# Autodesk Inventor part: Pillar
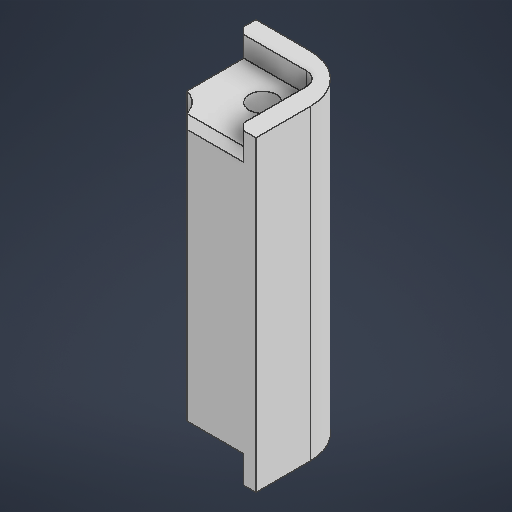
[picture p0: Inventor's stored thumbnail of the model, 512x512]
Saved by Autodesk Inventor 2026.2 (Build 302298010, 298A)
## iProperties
Created: 2026-04
Part Number: Pillar
Material: 일반
Document SubType Name: Modeling
Designer: work
Density: 1 g/cm^3
Appearance: 기본값
Author: work
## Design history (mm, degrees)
sketch "스케치1"
  geometry: L1 (0, 0)-(8, 0); L2 (0, 0)-(0, 8); L3 (8, 4)-(8, -7); L4 (8, -7)-(0, -7); L5 (8, 4)-(4, 4); L6 (4, 4)-(4, 8); L7 (4, 8)-(-7, 8); L8 (-7, 8)-(-7, 0); L9 (0, 0)-(-7, 0); L10 (0, 0)-(0, -7); C1 r 2 at (0, 0); A1 r 7 centre (0, 0) between (-7, 0) and (0, -7); 1 further point
  constraints: 20 end point, 3 perpendicular, 2 centre point, 2 horizontal, 2 point on circle, 2 point on line, 2 vertical, 1 coincident, 1 collinear, 1 concentric, 1 parallel, 1 tangent
  dimensions: "d0" = 4 diameter of C1; "d9" = 4 distance of L5.end L6.end; "d10" = 4 distance of L3.start L5.end; "d20" = 7 distance of L4.end point (0, 0); "d21" = 8 distance of L2.end point (0, 0); "d22" = 8 distance of L1.end point (0, 0)
extrude "돌출1" new body sketch "스케치1" distance "d11" = 45; taper "d12" = 0 deg
sketch "스케치2" dims "d23" = 4
  geometry: L1 (-4, -8)-(7, -8) reference; L2 (7, -8)-(7, 0) reference; L3 (0, 7)-(-8, 7) reference; L4 (-8, 7)-(-8, -4) reference; L5 (-8, -4)-(-4, -4) reference; L6 (-4, -4)-(-4, -8) reference; L7 (4.2, 2.2)-(4.2, -8); L8 (3.181, 4.2)-(-8, 4.2); C1 r 2 at (0, 0) reference; A1 r 7 centre (0, 0) between (7, 0) and (0, 7) reference; 2 further points
  constraints: 4 end point, 2 horizontal, 2 point on line, 1 perpendicular, 1 vertical, 3 other
  dimensions: "d24" = 2.8 distance between parallel lines of L2 L7; "d25" = 2.8 distance from line of L3.start L8
extrude "돌출2" cut sketch "스케치2" distance "d14" = 3; taper "d15" = 0 deg
node "작업 평면1"
fillet "모깎기1" dims "d16" = 4
chamfer "모따기1" distance "d17" = 1; stored, may be unused: second distance "d18" = 2, angle "d19" = 45 deg
node "솔리드1"
mirror "미러1"
node "투영된 루프1"
